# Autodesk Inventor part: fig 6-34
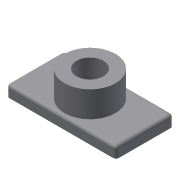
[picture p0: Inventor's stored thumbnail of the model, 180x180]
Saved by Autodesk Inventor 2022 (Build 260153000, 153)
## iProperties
Created: 2004-05
Part Number: fig 6-34
Document SubType Name: Modeling
Designer: CADCIM Technologies
Manufacturer: Standard
Standards Organization: Custom
Density: 1 g/cm^3
Material: Generic
Appearance: Default
Author: CADCIM Technologies
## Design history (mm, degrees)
sketch "Sketch1"
  geometry: L1 (-39.276, -18.692)-(33.721, -18.692); L2 (33.721, -18.692)-(33.721, 19.728); L3 (33.721, 19.728)-(-39.276, 19.728); L4 (-39.276, 19.728)-(-39.276, -18.692)
  constraints: 8 end point, 2 parallel, 1 horizontal, 1 perpendicular
extrude "Extrusion1" new body sketch "Sketch1" distance "d0" = 7.5; taper "d1" = 0 deg
sketch "Sketch2"
  geometry: C1 r 17 at (-2.778, 0.518)
  constraints: 1 centre point
  dimensions: "d16" = 34 diameter of C1
extrude "Extrusion2" join sketch "Sketch2" distance "d3" = 17.25; taper "d4" = 0 deg
hole "Hole1" diameter "d8" = 18; stored, may be unused: countersink angle "d12" = 90 deg, drill point angle "d14" = 118 deg; dims "d6" = 10, "d7" = 10, "d9" = 6, "d10" = 4, "d11" = 2, "d13" = 8
fillet "Fillet4" dims "d17" = 2
body "Solid1"
